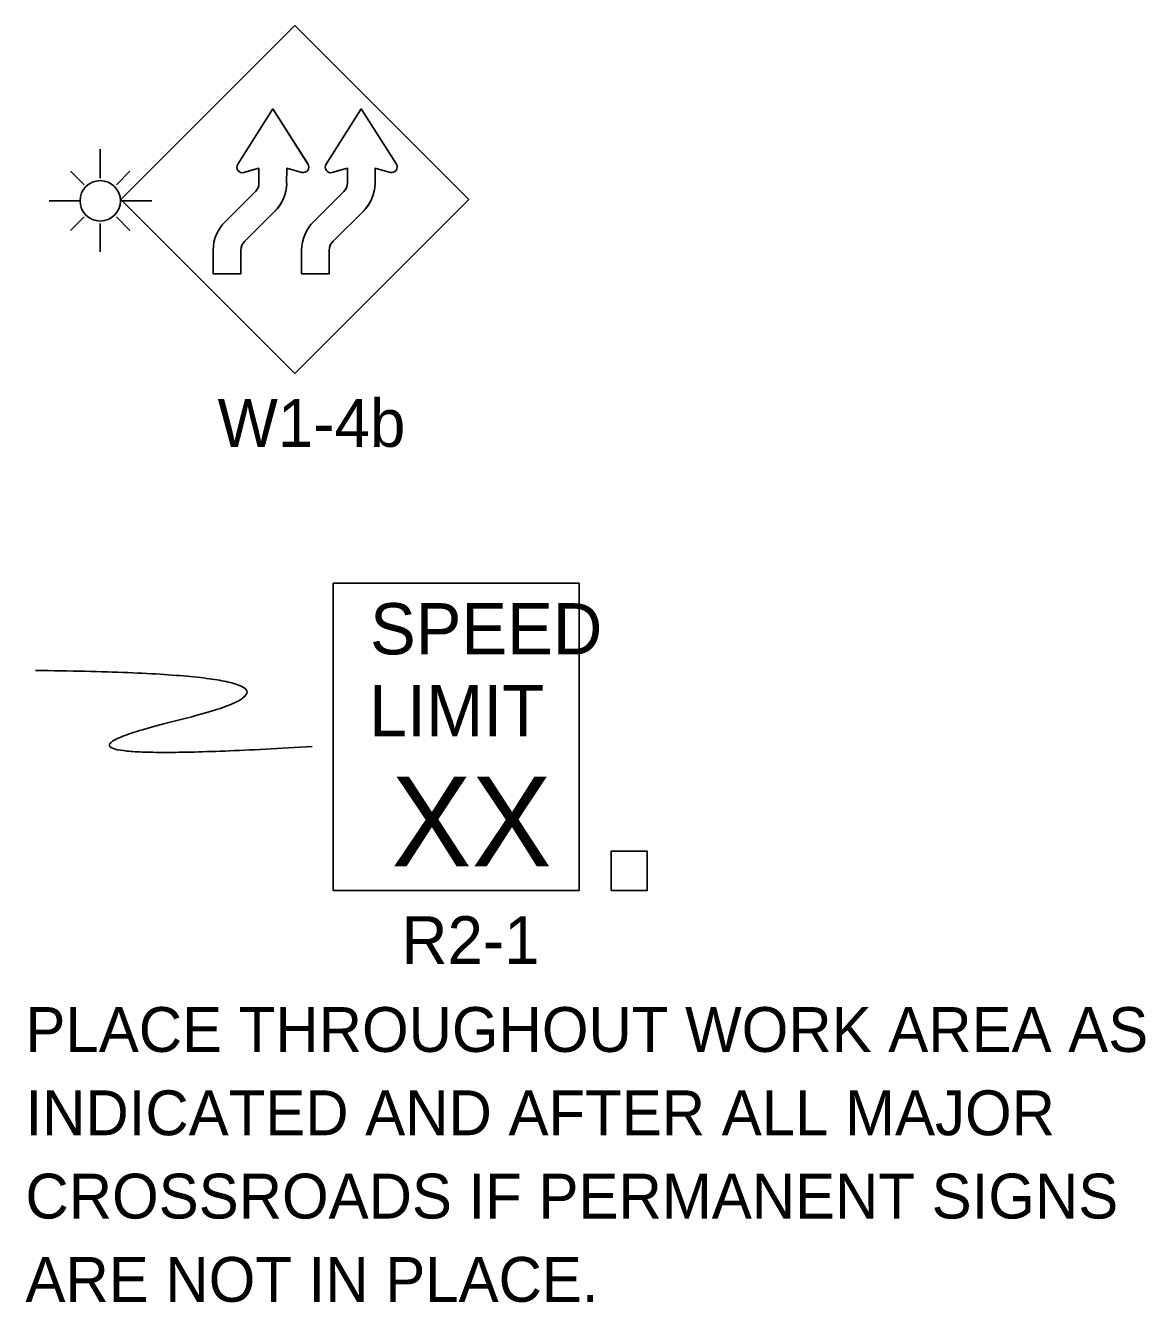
# Model space of a CAD drawing. Extents: x 16038 to 19504, y 5920 to 8321.
# Drawn here: x 17253.8 to 17428.7, y 7504 to 7703.3 of the extents above; entities that cross this region are included whole.
import ezdxf

# ---------------------------------------------------------------- set-up
doc = ezdxf.new("R2010")
doc.units = 0
doc.layers.add('TRAFFIC_SIGNS_PR', color=7, linetype='Continuous')

msp = doc.modelspace()

# ---------------------------------------------------------------- linework, layer by layer
at = {"layer": 'TRAFFIC_SIGNS_PR'}
for p, q in [((17295.86, 7703.28), (17268.71, 7676.12)), ((17323.01, 7676.12), (17295.86, 7703.28)), ((17265.49, 7679.47), (17265.49, 7683.97)), ((17262.97, 7678.43), (17260.87, 7680.54)), ((17268, 7678.43), (17270.11, 7680.54)), ((17268.71, 7676.12), (17295.86, 7648.97)), ((17284.99, 7672.66), (17289.71, 7677.37)), ((17289.71, 7677.37), (17284.99, 7672.66)), ((17295.86, 7648.97), (17323.01, 7676.12)), ((17298.79, 7672.66), (17303.5, 7677.37)), ((17303.51, 7677.37), (17298.79, 7672.66)), ((17262.33, 7675.92), (17257.49, 7675.92)), ((17268.64, 7675.92), (17273.52, 7675.92)), ((17288.05, 7669.61), (17292.76, 7674.32)), ((17288.05, 7669.61), (17292.76, 7674.32)), ((17301.84, 7669.61), (17306.56, 7674.32)), ((17301.84, 7669.61), (17306.56, 7674.32)), ((17262.97, 7673.4), (17260.87, 7671.29)), ((17265.49, 7667.95), (17265.49, 7672.36)), ((17268, 7673.4), (17270.11, 7671.3)), ((17283.13, 7664.54), (17283.13, 7668.24)), ((17287.45, 7664.54), (17287.45, 7668.24)), ((17296.93, 7664.54), (17296.93, 7668.24)), ((17301.24, 7664.54), (17301.24, 7668.24)), ((17283.13, 7664.54), (17287.45, 7664.54)), ((17296.93, 7664.54), (17301.24, 7664.54)), ((17301.83, 7616.28), (17340.23, 7616.28)), ((17301.83, 7568.28), (17301.83, 7616.28)), ((17340.23, 7568.28), (17340.23, 7616.28)), ((17301.83, 7568.28), (17340.23, 7568.28))]:
    msp.add_line(p, q, dxfattribs=at)
for points in [[(17297.92, 7681.65), (17292.43, 7690.26), (17286.95, 7681.65)], [(17297.91, 7681.65), (17292.43, 7690.26), (17286.95, 7681.65)], [(17311.71, 7681.65), (17306.23, 7690.26), (17300.75, 7681.65)], [(17311.71, 7681.65), (17306.23, 7690.26), (17300.75, 7681.65)], [(17287.91, 7680.35), (17290.27, 7681), (17290.27, 7678.7)], [(17287.91, 7680.35), (17288.75, 7680.58), (17290.27, 7681), (17290.27, 7678.7)], [(17294.58, 7678.63), (17294.59, 7681), (17296.95, 7680.35)], [(17294.58, 7678.63), (17294.59, 7681), (17296.95, 7680.35)], [(17301.71, 7680.35), (17304.07, 7681), (17304.07, 7678.7)], [(17301.71, 7680.35), (17302.54, 7680.58), (17304.07, 7681), (17304.07, 7678.7)], [(17308.38, 7678.63), (17308.39, 7681), (17310.75, 7680.35)], [(17308.38, 7678.63), (17308.39, 7681), (17310.75, 7680.35)], [(17283.13, 7668.24), (17283.13, 7664.54), (17287.45, 7664.54), (17287.45, 7668.24)], [(17296.92, 7668.24), (17296.93, 7664.54), (17301.24, 7664.54), (17301.24, 7668.24)]]:
    msp.add_lwpolyline(points, dxfattribs=at)
msp.add_lwpolyline([(17345.25, 7568.28), (17350.84, 7568.28), (17350.84, 7574.45), (17345.25, 7574.45)], close=True, dxfattribs=at)
msp.add_circle((17265.49, 7675.92), 3.15, dxfattribs=at)
for centre, radius, start, end in [((17287.68, 7681.18), 0.864, 147.5204, 285.3986), ((17287.68, 7681.18), 0.866, 147.5288, 285.3852), ((17297.18, 7681.19), 0.866, 254.6828, 32.2708), ((17297.18, 7681.19), 0.866, 254.6799, 32.2804), ((17294.1, 7669.93), 10.8, 74.68, 74.6808), ((17307.02, 7687.44), 10.8, 212.4569, 212.4665), ((17301.48, 7681.18), 0.864, 147.5204, 285.3986), ((17301.48, 7681.18), 0.866, 147.5288, 285.3852), ((17310.98, 7681.19), 0.866, 254.6828, 32.2708), ((17310.98, 7681.19), 0.866, 254.6799, 32.2804), ((17307.9, 7669.93), 10.8, 74.68, 74.6808), ((17320.82, 7687.44), 10.8, 212.4569, 212.4665), ((17288.42, 7678.7), 1.85, 314.2125, 0), ((17288.42, 7678.7), 1.85, 314.2123, 0.1238), ((17288.42, 7678.7), 6.17, 314.2125, 359.3819), ((17288.42, 7678.7), 6.17, 314.7687, 359.3755), ((17302.22, 7678.7), 1.85, 314.2125, 0), ((17302.21, 7678.7), 1.85, 314.2123, 0.1238), ((17302.22, 7678.7), 6.17, 314.2125, 359.3819), ((17302.21, 7678.7), 6.17, 314.7687, 359.3755), ((17289.29, 7668.24), 6.17, 134.2125, 180), ((17289.29, 7668.24), 6.17, 134.2125, 180), ((17289.29, 7668.24), 6.17, 134.2117, 180), ((17303.09, 7668.24), 6.17, 134.2125, 180), ((17303.09, 7668.24), 6.17, 134.2125, 180), ((17303.09, 7668.24), 6.17, 134.2117, 180), ((17289.29, 7668.24), 1.85, 132.372, 180), ((17289.29, 7668.24), 1.85, 134.2125, 180), ((17303.09, 7668.24), 1.85, 132.372, 180), ((17303.09, 7668.24), 1.85, 134.2125, 180)]:
    msp.add_arc(centre, radius, start, end, dxfattribs=at)
msp.add_open_spline([(17298.58, 7590.77), (17248.35, 7587.68), (17307.16, 7602.11), (17255.38, 7602.63)], degree=2, dxfattribs=at)

# ---------------------------------------------------------------- texts
for s, height, p in [('W1-4b', 7.44, (17283.82, 7637.53)), ('SPEED', 8, (17307.6, 7605.14)), ('LIMIT', 8, (17307.44, 7592.34)), ('XX', 14.031, (17310.94, 7572.04)), ('R2-1', 7.44, (17312.51, 7556.84)), ('PLACE THROUGHOUT WORK AREA AS', 7, (17253.81, 7543.1)), ('INDICATED AND AFTER ALL MAJOR', 7, (17253.81, 7530.1)), ('CROSSROADS IF PERMANENT SIGNS', 7, (17253.81, 7517.1)), ('ARE NOT IN PLACE.', 7, (17253.81, 7504.1))]:
    msp.add_text(s, height=height, dxfattribs=at).set_placement(p)

doc.saveas('drawing.dxf')
